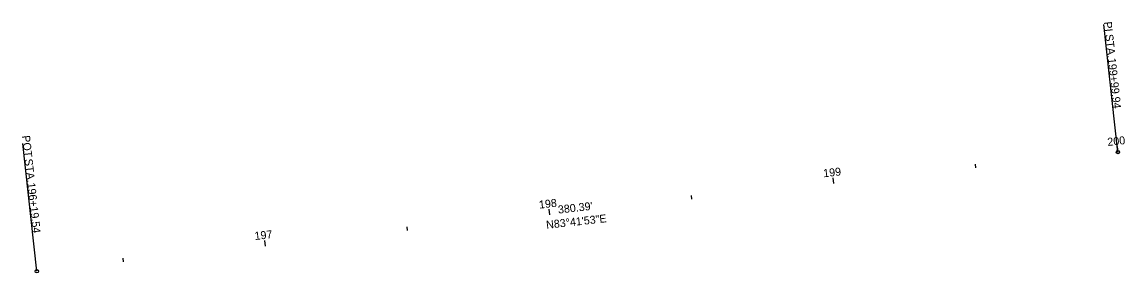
# Model space of a CAD drawing. Extents: x 1600023 to 1602131, y 285824 to 287284.
# Drawn here: x 1600022.9 to 1600408.6, y 286533.7 to 286621.6 of the extents above; entities that cross this region are included whole.
import ezdxf

# ---------------------------------------------------------------- set-up
doc = ezdxf.new("R2010")
doc.units = 0
for name, color, linetype in [('GE_P_Alignment_100_Bearings', 7, 'Continuous'), ('GE_P_Alignment_100_Cardinal_Points', 7, 'Continuous'), ('GE_P_Alignment_100_Distances', 7, 'Continuous'), ('GE_P_Alignment_100_Stations', 7, 'Continuous')]:
    doc.layers.add(name, color=color, linetype=linetype)

msp = doc.modelspace()

# ---------------------------------------------------------------- linework, layer by layer
at = {"layer": 'GE_P_Alignment_100_Cardinal_Points'}
for p, q in [((1600406.13, 286576.06), (1600401.22, 286620.8)), ((1600028.03, 286534.31), (1600023.1, 286579.04))]:
    msp.add_line(p, q, dxfattribs=at)
for centre in [(1600406.13, 286576.06), (1600028.03, 286534.31)]:
    msp.add_circle(centre, 0.6, dxfattribs=at)
at = {"layer": 'GE_P_Alignment_100_Stations'}
for p, q in [((1600406.19, 286576.07), (1600405.97, 286578.06)), ((1600356.49, 286570.58), (1600356.36, 286571.78)), ((1600306.8, 286565.1), (1600306.58, 286567.08)), ((1600257.1, 286559.61), (1600256.97, 286560.8)), ((1600207.4, 286554.12), (1600207.18, 286556.11)), ((1600157.7, 286548.63), (1600157.57, 286549.82)), ((1600108.01, 286543.14), (1600107.79, 286545.13)), ((1600058.31, 286537.65), (1600058.18, 286538.85))]:
    msp.add_line(p, q, dxfattribs=at)

# ---------------------------------------------------------------- texts
at = {"layer": 'GE_P_Alignment_100_Bearings'}
msp.add_text('N83°41\'53"E', height=2.8, rotation=6.3018, dxfattribs=at).set_placement((1600206.31, 286549.17))
at = {"layer": 'GE_P_Alignment_100_Cardinal_Points'}
for s, rotation, p in [('PI', 276.2675, (1600401.17, 286621.61)), (' STA. ', 276.2675, (1600401.54, 286618.24)), ('199+99.94', 276.2675, (1600402.57, 286608.85)), ('POT', 276.3018, (1600022.84, 286581.75)), (' STA. ', 276.3018, (1600023.63, 286574.59)), ('196+19.54', 276.3018, (1600024.67, 286565.2))]:
    msp.add_text(s, height=2.8, rotation=rotation, dxfattribs=at).set_placement(p)
at = {"layer": 'GE_P_Alignment_100_Distances'}
msp.add_text("380.39'", height=2.8, rotation=6.3018, dxfattribs=at).set_placement((1600210.44, 286554.5))
at = {"layer": 'GE_P_Alignment_100_Stations'}
for s, rotation, p in [('200', 6.2675, (1600402.59, 286578.19)), ('199', 6.3018, (1600303.22, 286567.22)), ('198', 6.3018, (1600203.81, 286556.24)), ('197', 6.3018, (1600104.34, 286545.25))]:
    msp.add_text(s, height=2.8, rotation=rotation, dxfattribs=at).set_placement(p)

doc.saveas('drawing.dxf')
